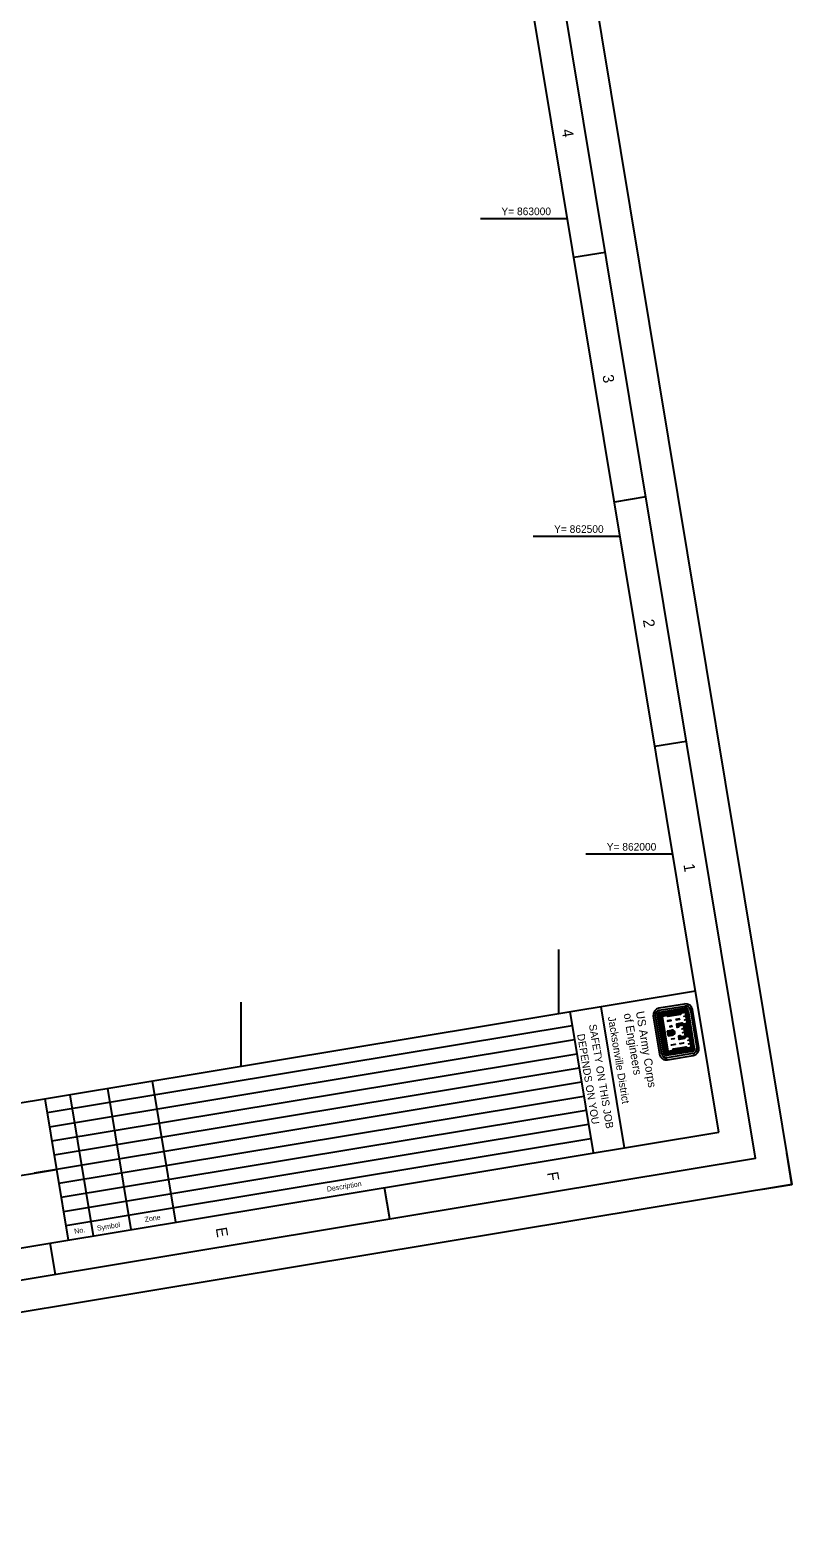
# Model space of a CAD drawing. Extents: x 574793 to 578867, y 860923 to 865820.
# Drawn here: x 577668 to 578867, y 860923 to 863296 of the extents above; entities that cross this region are included whole.
import ezdxf

# ---------------------------------------------------------------- set-up
doc = ezdxf.new("R2010")
doc.units = 0
for name, color, linetype in [('G-ANNO-NPLT', 7, 'Continuous'), ('G-ANNO-TEXT-LOGO', 7, 'Continuous'), ('G-ANNO-TEXT-TTLB', 7, 'Continuous'), ('G-ANNO-TTLB', 7, 'Continuous'), ('V-TOPO-COOR-STAT', 7, 'Continuous')]:
    doc.layers.add(name, color=color, linetype=linetype)

msp = doc.modelspace()

# ---------------------------------------------------------------- linework, layer by layer
at = {"layer": 'G-ANNO-NPLT'}
msp.add_lwpolyline([(578147.3, 865820.4), (578867.1, 861479.7), (575512.9, 860923.5), (574793.1, 865264.2)], close=True, dxfattribs=at)
msp.add_lwpolyline([(578817.7, 861471.5), (578867.1, 861479.7), (578858.9, 861529)], dxfattribs=at)
at = {"layer": 'G-ANNO-TEXT-LOGO'}
for p, q in [((578698.3, 861763.5), (578657.8, 861756.8)), ((578658.3, 861753.7), (578698.8, 861760.4)), ((578648.9, 861744.5), (578658.9, 861684.5)), ((578662.1, 861685.1), (578652.2, 861745)), ((578665.6, 861685.6), (578655.6, 861745.6)), ((578666.4, 861685.8), (578656.4, 861745.7)), ((578667.3, 861685.9), (578657.3, 861745.9)), ((578668.1, 861686.1), (578658.2, 861746)), ((578699.4, 861756.9), (578658.9, 861750.2)), ((578668.9, 861686.2), (578659, 861746.2)), ((578699.5, 861756), (578659.1, 861749.3)), ((578699.6, 861755.2), (578659.2, 861748.5)), ((578699.8, 861754.4), (578659.3, 861747.7)), ((578699.9, 861753.5), (578659.5, 861746.8)), ((578700.1, 861752.6), (578659.9, 861745.9)), ((578669.8, 861686.7), (578659.9, 861745.9)), ((578700.2, 861751.8), (578661, 861745.3)), ((578670.5, 861687.7), (578661, 861745.3)), ((578691.8, 861749.7), (578671, 861746.2)), ((578691, 861748.6), (578672.2, 861745.5)), ((578710.6, 861693.1), (578700.6, 861753.1)), ((578711.4, 861693.2), (578701.5, 861753.2)), ((578712.2, 861693.4), (578702.3, 861753.4)), ((578713.1, 861693.5), (578703.2, 861753.5)), ((578714, 861693.7), (578704.1, 861753.6)), ((578707.4, 861754.2), (578717.4, 861694.2)), ((578720.5, 861694.7), (578710.6, 861754.7)), ((578670.9, 861721.4), (578677.5, 861722.5)), ((578670.9, 861721.4), (578672.2, 861713.5)), ((578671, 861720.6), (578677.6, 861721.7)), ((578671.2, 861719.7), (578677.8, 861720.8)), ((578671.3, 861718.8), (578677.9, 861719.9)), ((578671.5, 861718), (578678.1, 861719.1)), ((578671.7, 861716.9), (578678.3, 861717.9)), ((578671.8, 861716.1), (578678.4, 861717.2)), ((578671.9, 861715.2), (578678.5, 861716.3)), ((578672.1, 861714.3), (578678.7, 861715.4)), ((578672.2, 861713.5), (578678.8, 861714.6)), ((578698.1, 861731.3), (578701.2, 861712.9)), ((578699, 861731.4), (578702.1, 861713.1)), ((578699.8, 861731.6), (578702.9, 861713.2)), ((578700.7, 861731.7), (578703.8, 861713.4)), ((578701.6, 861731.9), (578704.6, 861713.5)), ((578702.4, 861732), (578705.4, 861713.6)), ((578703.3, 861732.1), (578706.3, 861713.8)), ((578710.1, 861692.5), (578669.6, 861685.8)), ((578709.9, 861693.4), (578669.8, 861686.7)), ((578710.2, 861691.6), (578669.8, 861684.9)), ((578710.3, 861690.8), (578669.9, 861684.1)), ((578710.5, 861689.9), (578670, 861683.2)), ((578710.6, 861689.1), (578670.2, 861682.3)), ((578709.8, 861694.2), (578670.5, 861687.7)), ((578701, 861693.4), (578680.5, 861690)), ((578700, 861694.2), (578681.2, 861691.1)), ((578711.2, 861685.7), (578670.7, 861679)), ((578671.3, 861675.7), (578711.7, 861682.4))]:
    msp.add_line(p, q, dxfattribs=at)
for points in [[(578700.3, 861751.1), (578692.5, 861749.8), (578691.1, 861747.9), (578672.3, 861744.7), (578670.2, 861746.1), (578661.7, 861744.7), (578671, 861688.5), (578679.6, 861689.9), (578681.1, 861692), (578699.9, 861695.1), (578701.9, 861693.6), (578709.7, 861694.9), (578708.4, 861702.3), (578707.5, 861708), (578706.6, 861713.3), (578698.8, 861712), (578697.4, 861709.9), (578690.5, 861708.7), (578689.8, 861712.9), (578690.5, 861713), (578692.6, 861711.5), (578700.3, 861712.8), (578699.1, 861720.2), (578698.1, 861725.9), (578697.3, 861731.1), (578689.6, 861729.9), (578688.1, 861727.8), (578687.4, 861727.7), (578686.7, 861731.8), (578693.6, 861733), (578695.6, 861731.5), (578703.4, 861732.8), (578702.1, 861740.2), (578701.2, 861745.9), (578700.3, 861751.1)], [(578699.6, 861750.2), (578693.1, 861749.1), (578691.6, 861747), (578672.1, 861743.8), (578670, 861745.3), (578662.7, 861744), (578671.7, 861689.4), (578679, 861690.6), (578680.5, 861692.8), (578700, 861696), (578702.1, 861694.4), (578708.6, 861695.5), (578707.8, 861700.8), (578704.7, 861700.3), (578704.6, 861700.8), (578707.7, 861701.3), (578706.8, 861706.6), (578703.7, 861706.1), (578703.7, 861706.5), (578706.7, 861707), (578705.9, 861712.3), (578699.3, 861711.2), (578697.9, 861709.1), (578689.9, 861707.8), (578688.9, 861713.5), (578690.8, 861713.8), (578692.9, 861712.4), (578699.4, 861713.4), (578698.5, 861718.8), (578695.4, 861718.3), (578695.4, 861718.7), (578698.4, 861719.2), (578697.5, 861724.5), (578694.5, 861724), (578694.4, 861724.5), (578697.5, 861725), (578696.6, 861730.2), (578690.1, 861729.1), (578688.6, 861727.1), (578686.7, 861726.8), (578685.8, 861732.5), (578693.8, 861733.8), (578695.8, 861732.3), (578702.4, 861733.4), (578701.5, 861738.6), (578698.4, 861738.1), (578698.4, 861738.6), (578701.4, 861739.1), (578700.5, 861744.4), (578697.5, 861743.9), (578697.4, 861744.3), (578700.5, 861744.8), (578699.6, 861750.2)], [(578677.2, 861738.2), (578671.4, 861737.2), (578671.5, 861736.6), (578677.3, 861737.6), (578677.2, 861738.2)], [(578690.4, 861740.3), (578684.6, 861739.4), (578684.7, 861738.8), (578690.5, 861739.7), (578690.4, 861740.3)], [(578678.7, 861729.1), (578674.7, 861728.4), (578674.8, 861727.9), (578678.8, 861728.6), (578678.7, 861729.1)], [(578693.9, 861731.6), (578693.4, 861732), (578687.7, 861731.1), (578688.1, 861729.2), (578689.1, 861730.7), (578694.1, 861731.5)], [(578683.6, 861699.8), (578677.8, 861698.8), (578677.7, 861699.3), (578683.5, 861700.3), (578683.6, 861699.8)], [(578682.1, 861708.8), (578678.1, 861708.1), (578678, 861708.6), (578682, 861709.2), (578682.1, 861708.8)], [(578696.7, 861702), (578691, 861701), (578690.9, 861701.5), (578696.6, 861702.4), (578696.7, 861702)], [(578697.3, 861711.3), (578696.9, 861710.7), (578691.3, 861709.8), (578691, 861711.5), (578692.5, 861710.6), (578697.4, 861711.4)]]:
    msp.add_lwpolyline(points, dxfattribs=at)
for centre, major_axis, start_param, end_param in [((578700, 861753), (1.8, -10.6), 1.57078, 3.141576), ((578700, 861753), (1.23, -7.39), 1.57078, 3.141576), ((578659.5, 861746.2), (-1.8, 10.6), 6.28317, 7.853966), ((578659.5, 861746.2), (-1.23, 7.39), 6.28317, 7.853966), ((578659.5, 861746.2), (-0.66, 3.96), 6.28317, 7.853966), ((578659.5, 861746.2), (-0.52, 3.11), 6.28317, 7.853966), ((578659.5, 861746.2), (-0.37, 2.25), 6.28317, 7.853966), ((578659.5, 861746.2), (-0.23, 1.39), 6.28317, 7.853966), ((578659.5, 861746.2), (-0.089, 0.538), 6.28317, 7.853966), ((578700, 861753), (0.66, -3.96), 1.57078, 3.141576), ((578700, 861753), (0.52, -3.11), 1.57078, 3.141576), ((578700, 861753), (0.37, -2.25), 1.57078, 3.141576), ((578700, 861753), (0.23, -1.39), 1.57078, 3.141576), ((578700, 861753), (0.089, -0.538), 1.57078, 3.141576), ((578678, 861717), (-0.91, 5.48), 4.985832, 6.214359), ((578678, 861717), (-0.77, 4.62), 4.947465, 6.21436), ((578678, 861717), (-0.62, 3.77), 4.947465, 6.21436), ((578678, 861717), (-0.48, 2.91), 4.947465, 6.21436), ((578678, 861717), (-0.34, 2.05), 4.947465, 6.214359), ((578677.5, 861720), (0.34, -2.05), 0.068794, 1.335689), ((578677.5, 861720), (0.48, -2.91), 0.068794, 1.335689), ((578677.5, 861720), (0.62, -3.77), 0.068795, 1.335689), ((578677.5, 861720), (0.77, -4.62), 0.068795, 1.335689), ((578677.5, 861720), (0.91, -5.48), 0.068795, 1.29842), ((578710, 861693.1), (0.089, -0.538), 6.283169, 7.853965), ((578710, 861693.1), (0.23, -1.39), 6.283169, 7.853965), ((578710, 861693.1), (0.37, -2.25), 6.283169, 7.853965), ((578710, 861693.1), (0.52, -3.11), 6.283169, 7.853965), ((578710, 861693.1), (0.66, -3.96), 6.283169, 7.853965), ((578710, 861693.1), (1.23, -7.39), 6.28317, 7.853966), ((578710, 861693.1), (1.8, -10.6), 6.283169, 7.853965), ((578669.5, 861686.3), (1.8, -10.6), 4.712373, 6.28317), ((578669.5, 861686.3), (-1.23, 7.39), 1.570781, 3.141577), ((578669.5, 861686.3), (0.66, -3.96), 4.712373, 6.28317), ((578669.5, 861686.3), (0.52, -3.11), 4.712373, 6.28317), ((578669.5, 861686.3), (0.37, -2.25), 4.712373, 6.28317), ((578669.5, 861686.3), (0.23, -1.39), 4.712373, 6.28317), ((578669.5, 861686.3), (0.089, -0.538), 4.712373, 6.28317)]:
    msp.add_ellipse(centre, major_axis=major_axis, ratio=0.99964, start_param=start_param, end_param=end_param, dxfattribs=at)
at = {"layer": 'G-ANNO-TTLB'}
for p, q in [((578573.2, 862946.4), (578523.8, 862938.2)), ((578637, 862561.6), (578587.6, 862553.4)), ((578700.8, 862176.9), (578651.4, 862168.7)), ((578715.2, 861784), (575558.4, 861260.5)), ((578517.5, 861751.8), (578554.3, 861529.8)), ((578566.1, 861759.2), (578602.9, 861537.2)), ((578521.2, 861729.2), (577694.6, 861592.1)), ((578524.9, 861707), (577698.3, 861569.9)), ((578528.6, 861684.8), (577702, 861547.7)), ((578532.3, 861662.6), (577705.7, 861525.5)), ((577859.7, 861642.1), (577896.5, 861420.1)), ((578536, 861640.4), (577709.3, 861503.3)), ((578539.6, 861618.2), (577713, 861481.1)), ((577730.3, 861620.6), (577767.1, 861398.6)), ((577789.5, 861630.4), (577826.3, 861408.5)), ((577691, 861614.1), (577727.8, 861392.1)), ((578543.3, 861596), (577716.7, 861458.9)), ((578547, 861573.8), (577720.4, 861436.7)), ((578550.7, 861551.6), (577724.1, 861414.5)), ((576861.3, 861363.1), (577709.4, 861503.1)), ((577709.4, 861503.1), (577674.4, 861497.3)), ((578233.9, 861425.4), (578225.7, 861474.7)), ((577707.8, 861338.1), (577699.6, 861387.5))]:
    msp.add_line(p, q, dxfattribs=at)
for points in [[(574850.6, 865223), (575554, 860981), (578809.6, 861520.8), (578106.1, 865762.9)], [(578752.1, 861562), (578077.2, 865631.4), (574920.4, 865107.9), (575595.2, 861038.5)]]:
    msp.add_lwpolyline(points, close=True, dxfattribs=at)
at = {"layer": 'V-TOPO-COOR-STAT'}
for p, q in [((578376.8, 863000), (578513.6, 863000)), ((578459.7, 862500), (578596.5, 862500)), ((578542.6, 862000), (578679.4, 862000)), ((578500, 861748.3), (578500, 861849.6)), ((578000, 861665.4), (578000, 861766.7))]:
    msp.add_line(p, q, dxfattribs=at)

# ---------------------------------------------------------------- texts
at = {"layer": 'G-ANNO-TEXT-TTLB'}
for s, height, rotation, p in [('Jacksonville District', 11.9, 279.4155, (578577.4, 861742.9)), ('of Engineers', 13.086, 279.4155, (578602.2, 861748)), ('US Army Corps', 13.086, 279.4155, (578621.4, 861751.2)), ('DEPENDS ON YOU', 11.9, 279.4155, (578528.9, 861715.7)), ('SAFETY ON THIS JOB', 11.9, 279.4155, (578547.6, 861730.7)), ('Description', 8, 9.4155, (578135.6, 861468.2)), ('Zone', 8, 9.4155, (577848.8, 861420.4)), ('No.', 8, 9.4155, (577737.9, 861401.8)), ('Symbol', 8, 9.4155, (577773.7, 861406.7))]:
    msp.add_text(s, height=height, rotation=rotation, dxfattribs=at).set_placement(p)
at = {"layer": 'G-ANNO-TTLB'}
for s, p in [('4', (578504.6, 863139.1)), ('3', (578568.7, 862752.6)), ('2', (578632.5, 862367.8)), ('1', (578696.3, 861983.1)), ('F', (578481.5, 861498.1)), ('E', (577960, 861410.8))]:
    msp.add_text(s, height=17.5, rotation=279.4155, dxfattribs=at).set_placement(p)
at = {"layer": 'V-TOPO-COOR-STAT'}
for s, p in [('Y= 863000', (578409.8, 863005)), ('Y= 862500', (578492.7, 862505)), ('Y= 862000', (578575.6, 862005))]:
    msp.add_text(s, height=12, dxfattribs=at).set_placement(p)

doc.saveas('drawing.dxf')
